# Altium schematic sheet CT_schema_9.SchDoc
size 385 x 278 mm
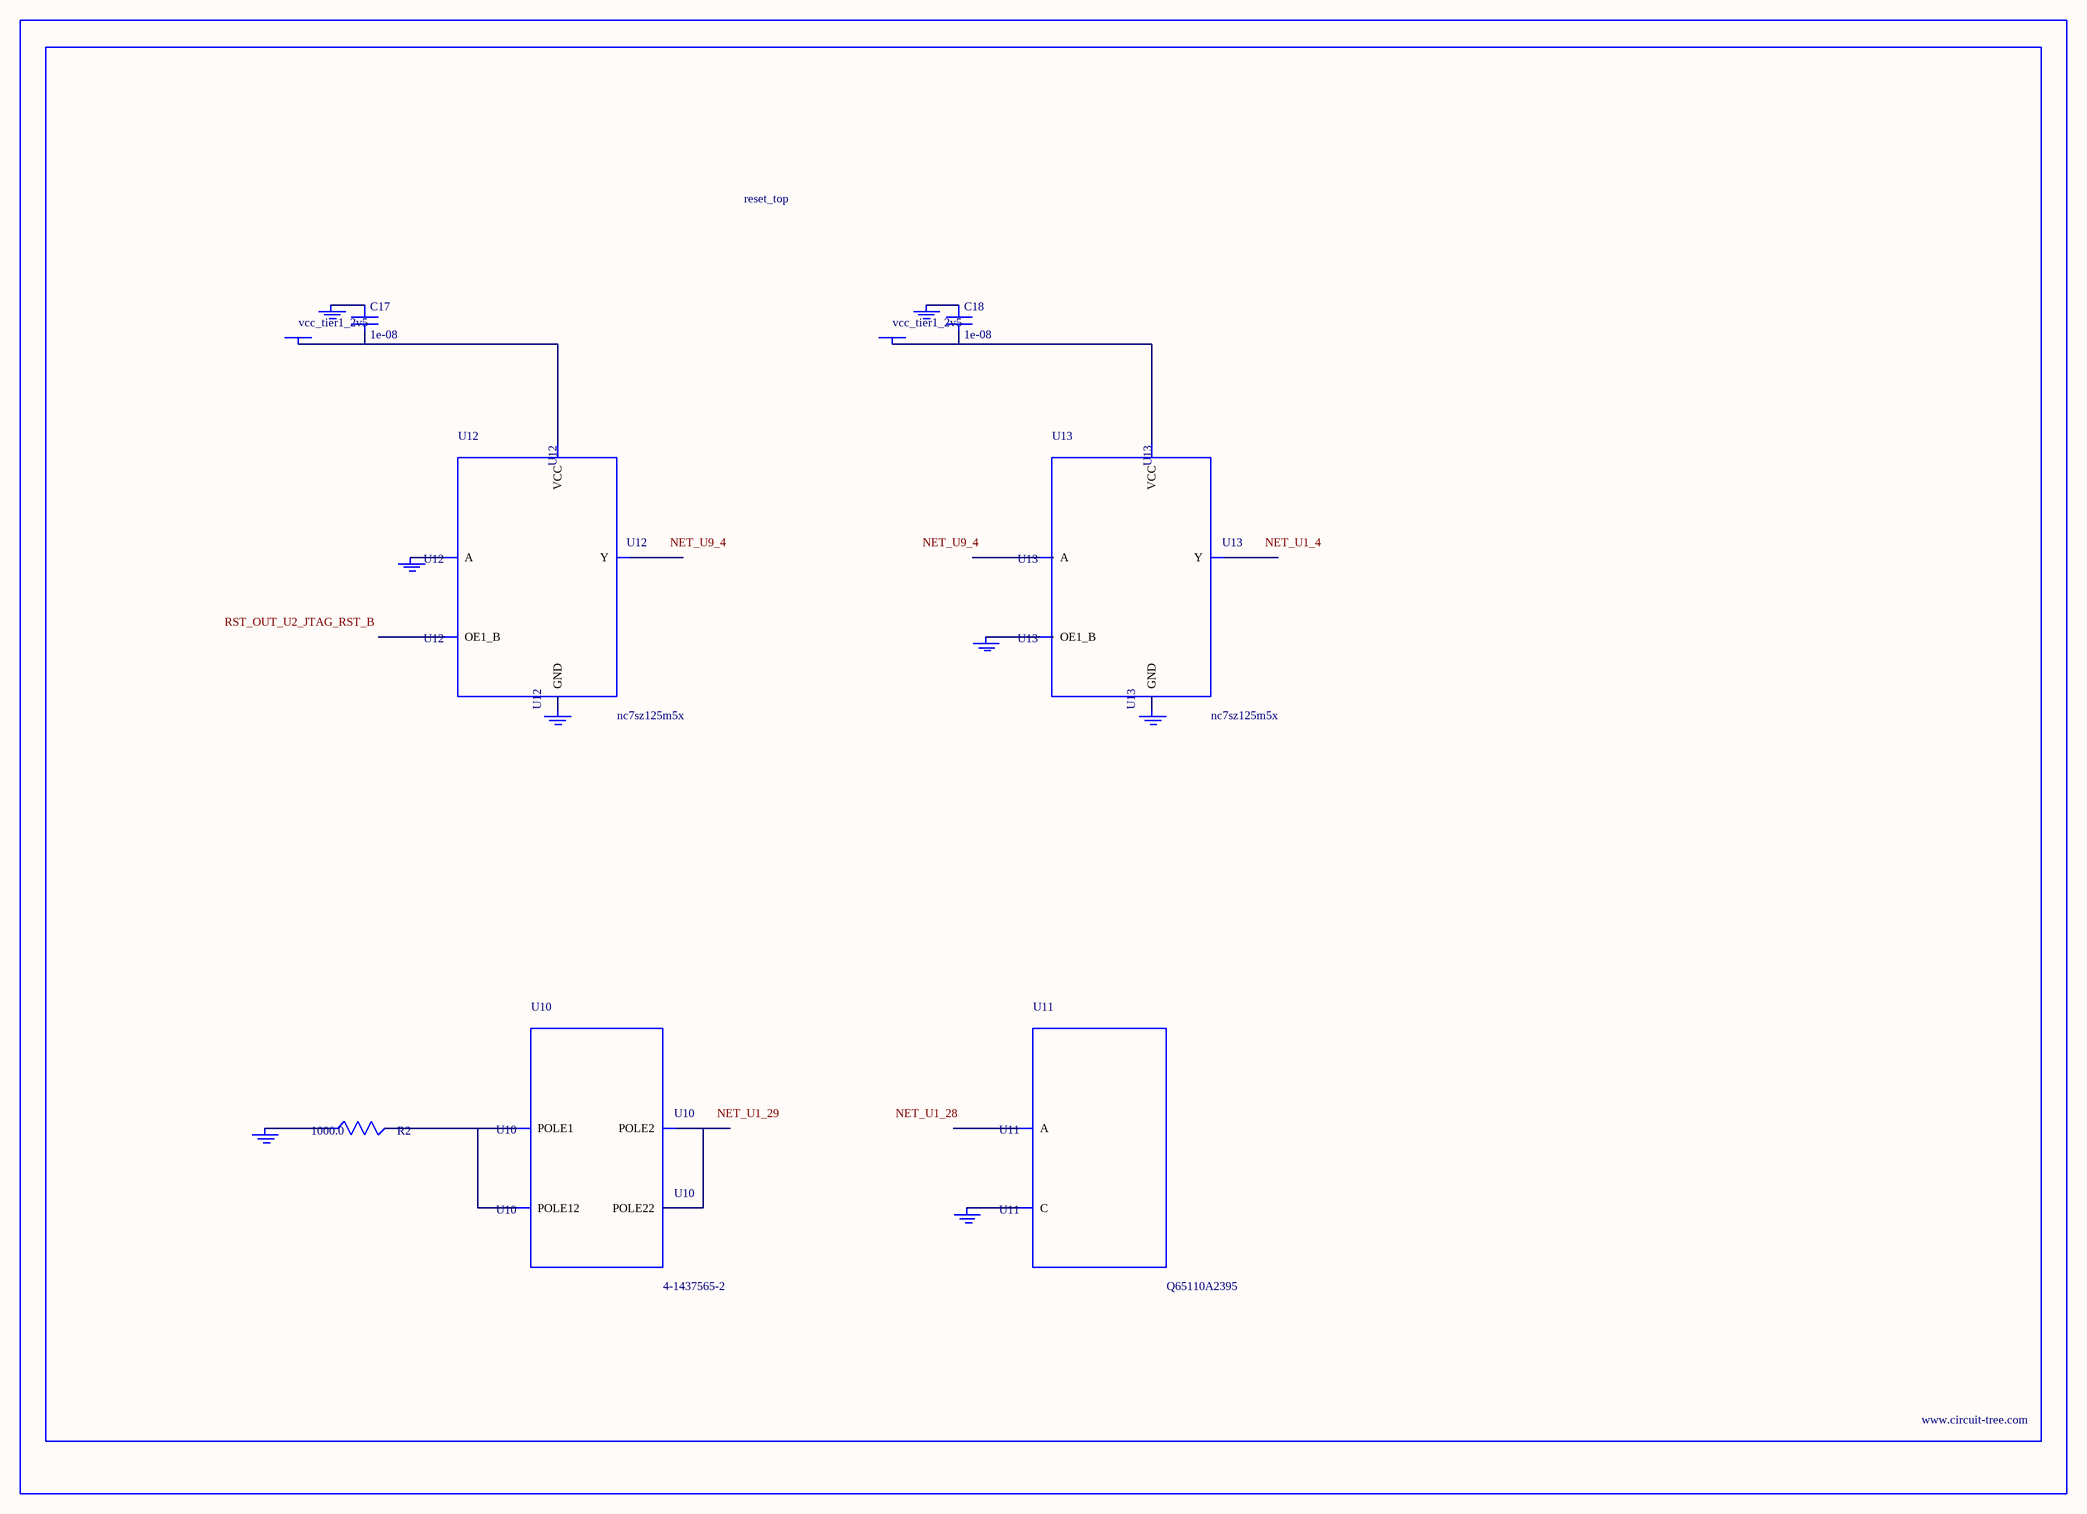
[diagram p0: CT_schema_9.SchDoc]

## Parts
BORDER8  (no value)
C17  1e-08  [C0402]
C18  1e-08  [C0402]
GND_INSTANCE_8_0  (no value)
GND_INSTANCE_8_1  (no value)
GND_INSTANCE_8_2  (no value)
GND_INSTANCE_8_3  (no value)
GND_INSTANCE_8_4  (no value)
GND_INSTANCE_8_5  (no value)
GND_INSTANCE_8_6  (no value)
GND_INSTANCE_8_7  (no value)
POWER_INSTANCE_8_0  vcc_tier1_2v5
POWER_INSTANCE_8_1  vcc_tier1_2v5
R2  1000.0  [R0603]
U10  4-1437565-2  [SW_4-1437565-2]
U11  Q65110A2395  [LGM67K-G1J2-24-Z]
U12  nc7sz125m5x  [NC7SZ125M5X]
U13  nc7sz125m5x  [NC7SZ125M5X]

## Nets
NetC17_1: C17.1 GND_INSTANCE_8_2.0(GND)
NetC17_2: C17.2 POWER_INSTANCE_8_0.0(PWR) U12.5(VCC)
NetC18_1: C18.1 GND_INSTANCE_8_5.0(GND)
NetC18_2: C18.2 POWER_INSTANCE_8_1.0(PWR) U13.5(VCC)
NetGND_INSTANCE_8_0_0: GND_INSTANCE_8_0.0(GND) R2.1
NetGND_INSTANCE_8_1_0: GND_INSTANCE_8_1.0(GND) U11.C
NetGND_INSTANCE_8_3_0: GND_INSTANCE_8_3.0(GND) U12.2(A)
NetGND_INSTANCE_8_4_0: GND_INSTANCE_8_4.0(GND) U12.3(GND)
NetGND_INSTANCE_8_6_0: GND_INSTANCE_8_6.0(GND) U13.1(OE1_B)
NetGND_INSTANCE_8_7_0: GND_INSTANCE_8_7.0(GND) U13.3(GND)
NetR2_2: R2.2 U10.1(POLE1) U10.2(POLE12)
NetU10_3: U10.3(POLE2) U10.4(POLE22)

Not connected (* = marked no-connect by the designer): U11 A; U12 1(OE1_B) 4(Y); U13 2(A) 4(Y)

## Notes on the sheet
- Labels drawn without touching a wire or pin: NET_U1_4, NET_U1_28, NET_U1_29, NET_U9_4, RST_OUT_U2_JTAG_RST_B

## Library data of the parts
BORDER8 = BORDER_PAGE8
C17 C18 = C0402C103K3RAC
GND_INSTANCE_8_0-GND_INSTANCE_8_7 = GND
POWER_INSTANCE_8_0 POWER_INSTANCE_8_1 = PWR
R2 = RC0603JR-071KL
